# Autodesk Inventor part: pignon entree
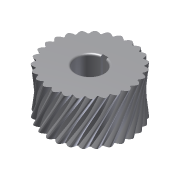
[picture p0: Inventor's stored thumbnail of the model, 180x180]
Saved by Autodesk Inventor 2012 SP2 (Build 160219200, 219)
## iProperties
Created: 2013-04
Part Number: pignon entree
Material: Default
Document SubType Name: Modeling
Designer: papa
Density: 1 g/cm^3
Mass: 9.35943 g
Surface Area: 35.1732 cm^2
Volume: 9.35943 cm^3
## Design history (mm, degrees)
node "pignon entree1"
sketch "Esquisse1"
  geometry: L1 (5.637, -7.885)-(5.591, -7.702) reference; L2 (3.651, -8.192)-(3.697, -8.374) reference; L3 (5.591, -7.702)-(3.651, -8.192) reference; C1 r 14.9 at (6.039, -13.571); A1 r 14.2 centre (6.039, -13.571) between (1.179, -0.229) and (0.806, -0.371) reference; A2 r 15.425 centre (6.039, -13.571) between (-0.857, 0.226) and (-1.301, -0.005) reference; A3 r 14.2 centre (6.039, -13.571) between (-1.767, -1.709) and (-2.098, -1.933) reference; A4 r 15.425 centre (6.039, -13.571) between (-3.853, -1.736) and (-4.232, -2.063) reference; A5 r 14.2 centre (6.039, -13.571) between (-4.292, -3.829) and (-4.562, -4.124) reference; A6 r 15.425 centre (6.039, -13.571) between (-6.316, -4.337) and (-6.609, -4.742) reference; A7 r 14.2 centre (6.039, -13.571) between (-6.26, -6.474) and (-6.455, -6.823) reference; A8 r 15.425 centre (6.039, -13.571) between (-8.112, -7.435) and (-8.304, -7.897) reference; A9 r 14.2 centre (6.039, -13.571) between (-7.565, -9.502) and (-7.674, -9.886) reference; A10 r 15.425 centre (6.039, -13.571) between (-9.146, -10.864) and (-9.226, -11.358) reference; A11 r 14.2 centre (6.039, -13.571) between (-8.137, -12.749) and (-8.154, -13.148) reference; A12 r 15.425 centre (6.039, -13.571) between (-9.361, -14.439) and (-9.325, -14.938) reference; A13 r 14.2 centre (6.039, -13.571) between (-7.944, -16.041) and (-7.869, -16.433) reference; A14 r 15.425 centre (6.039, -13.571) between (-8.745, -17.967) and (-8.595, -18.444) reference; A15 r 14.2 centre (6.039, -13.571) between (-6.998, -19.199) and (-6.834, -19.563) reference; A16 r 15.425 centre (6.039, -13.571) between (-7.333, -21.258) and (-7.077, -21.688) reference; A17 r 14.2 centre (6.039, -13.571) between (-5.348, -22.054) and (-5.105, -22.371) reference; A18 r 15.425 centre (6.039, -13.571) between (-5.2, -24.135) and (-4.851, -24.494) reference; A19 r 14.2 centre (6.039, -13.571) between (-3.085, -24.451) and (-2.775, -24.704) reference; A20 r 15.425 centre (6.039, -13.571) between (-2.461, -26.442) and (-2.039, -26.711) reference; A21 r 14.2 centre (6.039, -13.571) between (-0.33, -26.262) and (0.03, -26.436) reference; A22 r 15.425 centre (6.039, -13.571) between (0.737, -28.055) and (1.209, -28.22) reference; A23 r 14.2 centre (6.039, -13.571) between (2.769, -27.389) and (3.159, -27.476) reference; A24 r 15.425 centre (6.039, -13.571) between (4.22, -28.888) and (4.718, -28.939) reference; A25 r 14.2 centre (6.039, -13.571) between (6.043, -27.771) and (6.443, -27.765) reference; A26 r 15.425 centre (6.039, -13.571) between (7.802, -28.894) and (8.297, -28.829) reference; A27 r 14.2 centre (6.039, -13.571) between (9.318, -27.387) and (9.705, -27.289) reference; A28 r 15.425 centre (6.039, -13.571) between (11.288, -28.075) and (11.755, -27.897) reference; A29 r 14.2 centre (6.039, -13.571) between (12.416, -26.259) and (12.77, -26.074) reference; A30 r 15.425 centre (6.039, -13.571) between (14.491, -26.474) and (14.905, -26.193) reference; A31 r 14.2 centre (6.039, -13.571) between (15.17, -24.446) and (15.472, -24.185) reference; A32 r 15.425 centre (6.039, -13.571) between (17.239, -24.177) and (17.577, -23.808) reference; A33 r 14.2 centre (6.039, -13.571) between (17.432, -22.047) and (17.666, -21.724) reference; A34 r 15.425 centre (6.039, -13.571) between (19.383, -21.308) and (19.627, -20.871) reference; A35 r 14.2 centre (6.039, -13.571) between (19.08, -19.191) and (19.233, -18.823) reference; A36 r 15.425 centre (6.039, -13.571) between (20.808, -18.022) and (20.944, -17.541) reference; A37 r 14.2 centre (6.039, -13.571) between (20.024, -16.033) and (20.088, -15.638) reference; A38 r 15.425 centre (6.039, -13.571) between (21.436, -14.496) and (21.458, -13.997) reference; A39 r 14.2 centre (6.039, -13.571) between (20.215, -12.741) and (20.186, -12.343) reference; A40 r 15.425 centre (6.039, -13.571) between (21.235, -10.921) and (21.141, -10.43) reference; A41 r 14.2 centre (6.039, -13.571) between (19.642, -9.494) and (19.522, -9.113) reference; A42 r 15.425 centre (6.039, -13.571) between (20.214, -7.488) and (20.009, -7.032) reference; A43 r 14.2 centre (6.039, -13.571) between (18.335, -6.467) and (18.13, -6.124) reference; A44 r 15.425 centre (6.039, -13.571) between (18.429, -4.383) and (18.125, -3.986) reference; A45 r 14.2 centre (6.039, -13.571) between (16.365, -3.823) and (16.087, -3.537) reference; A46 r 15.425 centre (6.039, -13.571) between (15.976, -1.773) and (15.589, -1.458) reference; A47 r 14.2 centre (6.039, -13.571) between (13.839, -1.705) and (13.502, -1.49) reference; A48 r 15.425 centre (6.039, -13.571) between (12.988, 0.2) and (12.538, 0.418) reference; A49 r 14.2 centre (6.039, -13.571) between (10.892, -0.226) and (10.515, -0.095) reference; A50 r 15.425 centre (6.039, -13.571) between (9.624, 1.431) and (9.136, 1.54) reference; A51 r 14.2 centre (6.039, -13.571) between (7.684, 0.534) and (7.287, 0.574) reference; A52 r 15.425 centre (6.039, -13.571) between (6.068, 1.854) and (5.568, 1.847) reference; A53 r 14.2 centre (6.039, -13.571) between (4.387, 0.533) and (3.991, 0.481) reference; A54 r 15.425 centre (6.039, -13.571) between (2.51, 1.445) and (2.025, 1.322) reference; A55 r 5.7 centre (6.039, -13.571) between (3.697, -8.374) and (5.637, -7.885) reference
  constraints: 1 centre point, 1 coincident, 1 concentric, 54 other
  dimensions: "d0" = 29.8 diameter of C1
node "pignon entree"
node "Base1"
